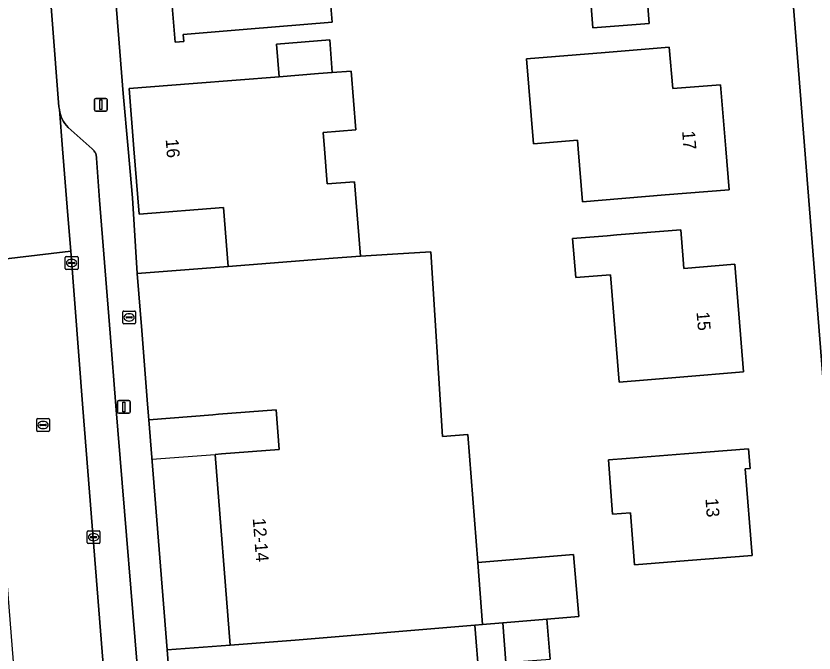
# Model space of a CAD drawing. Extents: x 157793 to 159380, y 380877 to 382313.
# Drawn here: x 158144.9 to 158207.1, y 381210.7 to 381260.3 of the extents above; entities that cross this region are included whole.
import ezdxf

# ---------------------------------------------------------------- set-up
doc = ezdxf.new("R2010")
doc.units = 0
for name, color, linetype in [('IMGEO_Brandkraan', 7, 'Continuous'), ('IMGEO_Erf', 7, 'Continuous'), ('IMGEO_Kolk', 7, 'Continuous'), ('IMGEO_Lichtmast', 7, 'Continuous'), ('IMGEO_Pand', 7, 'Continuous'), ('IMGEO_Pand_nummerreeks', 7, 'Continuous'), ('IMGEO_Pand_overbouw', 7, 'Continuous'), ('IMGEO_Parkeervlak_open', 7, 'Continuous'), ('IMGEO_Rijbaan_lokaal_gesloten', 7, 'Continuous'), ('IMGEO_Rioolput', 7, 'Continuous'), ('IMGEO_Voetpad_open', 7, 'Continuous')]:
    doc.layers.add(name, color=color, linetype=linetype)

msp = doc.modelspace()

# ---------------------------------------------------------------- linework, layer by layer
at = {"layer": 'IMGEO_Brandkraan'}
for p, q in [((158153.194, 381236.435), (158153.194, 381237.287)), ((158153.269, 381237.361), (158154.121, 381237.361)), ((158153.453, 381236.855), (158153.453, 381236.867)), ((158153.496, 381236.904), (158153.894, 381236.904)), ((158153.682, 381237.141), (158153.707, 381237.141)), ((158153.937, 381236.867), (158153.937, 381236.855)), ((158154.195, 381237.287), (158154.195, 381236.435)), ((158154.121, 381236.361), (158153.269, 381236.361)), ((158153.891, 381236.818), (158153.493, 381236.818)), ((158153.705, 381236.581), (158153.68, 381236.581))]:
    msp.add_line(p, q, dxfattribs=at)
for points in [[(158153.194, 381236.435), (158153.194, 381237.287)], [(158153.269, 381237.361), (158154.121, 381237.361)], [(158154.195, 381237.287), (158154.195, 381236.435)], [(158154.121, 381236.361), (158153.269, 381236.361)]]:
    msp.add_lwpolyline(points, dxfattribs=at)
for centre, radius, start, end in [((158153.271, 381237.285), 0.0765, 91.55205, 178.44795), ((158153.271, 381237.285), 0.0765, 91.55205, 178.44795), ((158153.493, 381236.864), 0.0403, 85.87752, 175.75265), ((158153.898, 381236.866), 0.0386, 1.73085, 96.63898), ((158154.119, 381237.285), 0.0765, 1.55205, 88.44795), ((158154.119, 381237.285), 0.0765, 1.55205, 88.44795), ((158153.271, 381236.437), 0.0765, 181.55205, 268.44795), ((158153.271, 381236.437), 0.0765, 181.55205, 268.44795), ((158153.49, 381236.854), 0.0366, 178.93798, 274.71019), ((158153.894, 381236.861), 0.043, 264.86636, 352.45326), ((158154.119, 381236.437), 0.0765, 271.55205, 358.44795), ((158154.119, 381236.437), 0.0765, 271.55205, 358.44795)]:
    msp.add_arc(centre, radius, start, end, dxfattribs=at)
for centre, major_axis, ratio, start_param, end_param in [((158153.681, 381236.861), (-0.387, 0.002), 0.722429, 4.712389, 7.853982), ((158153.706, 381236.861), (-0.39, 0.002), 0.717154, 1.570796, 4.712389)]:
    msp.add_ellipse(centre, major_axis=major_axis, ratio=ratio, start_param=start_param, end_param=end_param, dxfattribs=at)
at = {"layer": 'IMGEO_Erf'}
for points in [[(158217.503, 381108.594), (158207.836, 381230.9), (158200.897, 381318.677)], [(158168.188, 381275.758), (158169.503, 381259.859), (158162.895, 381259.313), (158157.911, 381258.901), (158157.957, 381258.343), (158157.27, 381258.287), (158156.726, 381264.864)], [(158151.631, 381274.599), (158153.242, 381254.297), (158153.62, 381250), (158153.955, 381246.186), (158154.327, 381240.281), (158161.404, 381240.838), (158161.045, 381245.426), (158154.465, 381244.912), (158154.068, 381250), (158153.701, 381254.693), (158158.686, 381255.083), (158165.381, 381255.607), (158165.183, 381258.147), (158169.325, 381258.471), (158169.524, 381255.932), (158170.991, 381256.047), (158171.349, 381251.472), (158168.814, 381251.273), (158168.914, 381250), (158169.128, 381247.273), (158171.257, 381247.409), (158171.71, 381241.622), (158174.222, 381241.782), (158177.203, 381241.972), (158178.12, 381227.586), (158180.078, 381227.739), (158180.857, 381217.78), (158188.317, 381218.406), (158188.723, 381213.573), (158186.249, 381213.365), (158186.492, 381210.258)], [(158183.047, 381209.988), (158182.805, 381213.077), (158181.235, 381212.945), (158180.637, 381212.898), (158180.967, 381208.681)]]:
    msp.add_lwpolyline(points, dxfattribs=at)
for points in [[(158182.446, 381266.828), (158181.783, 381275.315), (158186.626, 381275.693), (158191.61, 381276.082), (158191.916, 381272.173), (158198.287, 381272.671), (158198.947, 381264.211), (158193.902, 381263.817), (158194.219, 381259.76), (158189.827, 381259.417), (158189.51, 381263.474), (158189.207, 381267.356)], [(158189.027, 381245.874), (158188.689, 381250), (158188.635, 381250.662), (158185.197, 381250.38), (158184.655, 381256.988), (158190.795, 381257.491), (158195.778, 381257.9), (158196.042, 381254.682), (158199.768, 381254.987), (158200.177, 381250), (158200.439, 381246.81), (158195.456, 381246.401)], [(158188.486, 381239.97), (158188.241, 381243.01), (158190.944, 381243.228), (158191.694, 381243.288), (158196.677, 381243.69), (158196.852, 381241.365), (158196.904, 381240.676), (158200.884, 381241.003), (158201.571, 381232.617), (158196.588, 381232.208), (158191.875, 381231.822), (158191.192, 381240.189)], [(158160.403, 381226.199), (158160.902, 381226.238), (158165.388, 381226.589), (158165.147, 381229.669), (158160.662, 381229.318), (158160.215, 381229.283), (158155.23, 381228.893), (158155.463, 381225.953), (158156.652, 381210.965), (158161.565, 381211.348)], [(158191.03, 381225.77), (158192.426, 381225.879), (158196.971, 381226.235), (158201.955, 381226.625), (158202.075, 381225.095), (158201.701, 381225.066), (158202.229, 381218.318), (158197.245, 381217.928), (158193.074, 381217.602), (158192.757, 381221.652), (158191.361, 381221.543)]]:
    msp.add_lwpolyline(points, close=True, dxfattribs=at)
at = {"layer": 'IMGEO_Kolk'}
for p, q in [((158148.71, 381240.679), (158148.71, 381241.531)), ((158148.785, 381241.605), (158149.637, 381241.605)), ((158149.198, 381241.385), (158149.223, 381241.385)), ((158149.711, 381241.531), (158149.711, 381240.679)), ((158149.637, 381240.605), (158148.785, 381240.605)), ((158148.969, 381241.099), (158148.969, 381241.111)), ((158149.407, 381241.062), (158149.009, 381241.062)), ((158149.012, 381241.148), (158149.41, 381241.148)), ((158149.221, 381240.825), (158149.196, 381240.825)), ((158149.453, 381241.111), (158149.453, 381241.099)), ((158150.42, 381219.324), (158150.42, 381220.176)), ((158150.495, 381220.25), (158151.347, 381220.25)), ((158151.421, 381220.176), (158151.421, 381219.324)), ((158150.679, 381219.744), (158150.679, 381219.756)), ((158151.117, 381219.707), (158150.719, 381219.707)), ((158150.722, 381219.793), (158151.12, 381219.793)), ((158150.931, 381219.47), (158150.906, 381219.47)), ((158150.908, 381220.03), (158150.933, 381220.03)), ((158151.163, 381219.756), (158151.163, 381219.744)), ((158151.347, 381219.25), (158150.495, 381219.25))]:
    msp.add_line(p, q, dxfattribs=at)
for points in [[(158148.71, 381240.679), (158148.71, 381241.531)], [(158148.785, 381241.605), (158149.637, 381241.605)], [(158149.711, 381241.531), (158149.711, 381240.679)], [(158149.637, 381240.605), (158148.785, 381240.605)], [(158150.42, 381219.324), (158150.42, 381220.176)], [(158150.495, 381220.25), (158151.347, 381220.25)], [(158151.421, 381220.176), (158151.421, 381219.324)], [(158151.347, 381219.25), (158150.495, 381219.25)]]:
    msp.add_lwpolyline(points, dxfattribs=at)
for centre, radius, start, end in [((158148.787, 381241.529), 0.0765, 91.55205, 178.44795), ((158148.787, 381241.529), 0.0765, 91.55205, 178.44795), ((158149.635, 381241.529), 0.0765, 1.55205, 88.44795), ((158149.635, 381241.529), 0.0765, 1.55205, 88.44795), ((158148.787, 381240.681), 0.0765, 181.55205, 268.44795), ((158148.787, 381240.681), 0.0765, 181.55205, 268.44795), ((158149.009, 381241.108), 0.0403, 85.87752, 175.75265), ((158149.006, 381241.098), 0.0366, 178.93798, 274.71019), ((158149.41, 381241.105), 0.043, 264.86636, 352.45326), ((158149.414, 381241.11), 0.0386, 1.73085, 96.63898), ((158149.635, 381240.681), 0.0765, 271.55205, 358.44795), ((158149.635, 381240.681), 0.0765, 271.55205, 358.44795), ((158150.497, 381220.174), 0.0765, 91.55205, 178.44795), ((158150.497, 381220.174), 0.0765, 91.55205, 178.44795), ((158151.345, 381220.174), 0.0765, 1.55205, 88.44795), ((158151.345, 381220.174), 0.0765, 1.55205, 88.44795), ((158150.719, 381219.753), 0.0403, 85.87752, 175.75265), ((158150.716, 381219.743), 0.0366, 178.93798, 274.71019), ((158151.12, 381219.75), 0.043, 264.86636, 352.45326), ((158151.124, 381219.755), 0.0386, 1.73085, 96.63898), ((158150.497, 381219.326), 0.0765, 181.55205, 268.44795), ((158150.497, 381219.326), 0.0765, 181.55205, 268.44795), ((158151.345, 381219.326), 0.0765, 271.55205, 358.44795), ((158151.345, 381219.326), 0.0765, 271.55205, 358.44795)]:
    msp.add_arc(centre, radius, start, end, dxfattribs=at)
for centre, major_axis, ratio, start_param, end_param in [((158149.197, 381241.105), (-0.387, 0.002), 0.722429, 4.712389, 7.853982), ((158149.222, 381241.105), (-0.39, 0.002), 0.717154, 1.570796, 4.712389), ((158150.907, 381219.75), (-0.387, 0.002), 0.722429, 4.712389, 7.853982), ((158150.932, 381219.75), (-0.39, 0.002), 0.717154, 1.570796, 4.712389)]:
    msp.add_ellipse(centre, major_axis=major_axis, ratio=ratio, start_param=start_param, end_param=end_param, dxfattribs=at)
at = {"layer": 'IMGEO_Lichtmast'}
for p, q in [((158150.987, 381253.02), (158150.987, 381253.82)), ((158150.987, 381253.82), (158150.987, 381253.02)), ((158151.087, 381253.92), (158151.877, 381253.92)), ((158151.877, 381253.92), (158151.087, 381253.92)), ((158151.977, 381253.82), (158151.977, 381253.02)), ((158151.977, 381253.02), (158151.977, 381253.82)), ((158151.877, 381252.92), (158151.087, 381252.92)), ((158151.087, 381252.92), (158151.877, 381252.92)), ((158152.792, 381229.494), (158152.792, 381230.294)), ((158152.792, 381230.294), (158152.792, 381229.494)), ((158152.892, 381230.394), (158153.682, 381230.394)), ((158153.682, 381230.394), (158152.892, 381230.394)), ((158153.782, 381230.294), (158153.782, 381229.494)), ((158153.782, 381229.494), (158153.782, 381230.294)), ((158153.682, 381229.394), (158152.892, 381229.394)), ((158152.892, 381229.394), (158153.682, 381229.394))]:
    msp.add_line(p, q, dxfattribs=at)
for points in [[(158151.407, 381253.795), (158151.557, 381253.795), (158151.557, 381253.045), (158151.407, 381253.045), (158151.407, 381253.795)], [(158153.212, 381230.269), (158153.362, 381230.269), (158153.362, 381229.519), (158153.212, 381229.519), (158153.212, 381230.269)]]:
    msp.add_lwpolyline(points, dxfattribs=at)
for centre, start, end in [((158151.087, 381253.82), 90, 180), ((158151.087, 381253.82), 90, 180), ((158151.877, 381253.82), 0, 90), ((158151.877, 381253.82), 360, 90), ((158151.087, 381253.02), 180, 270), ((158151.087, 381253.02), 180, 270), ((158151.877, 381253.02), 270, 0), ((158151.877, 381253.02), 270, 0), ((158152.892, 381230.294), 90, 180), ((158152.892, 381230.294), 90, 180), ((158153.682, 381230.294), 0, 90), ((158153.682, 381230.294), 360, 90), ((158152.892, 381229.494), 180, 270), ((158152.892, 381229.494), 180, 270), ((158153.682, 381229.494), 270, 0), ((158153.682, 381229.494), 270, 0)]:
    msp.add_arc(centre, 0.1, start, end, dxfattribs=at)
at = {"layer": 'IMGEO_Pand'}
for points in [[(158193.902, 381263.817), (158198.947, 381264.211), (158198.287, 381272.671), (158191.916, 381272.173), (158191.61, 381276.082), (158186.626, 381275.693), (158181.783, 381275.315), (158182.446, 381266.828), (158189.207, 381267.356), (158189.51, 381263.474), (158189.827, 381259.417), (158194.219, 381259.76)], [(158163.343, 381275.531), (158156.582, 381274.995), (158156.623, 381274.491), (158156.705, 381273.503), (158157.03, 381269.555), (158156.433, 381269.506), (158156.548, 381268.101), (158157.147, 381268.15), (158157.414, 381264.921), (158156.726, 381264.864), (158157.27, 381258.287), (158157.957, 381258.343), (158157.911, 381258.901), (158162.895, 381259.313), (158169.503, 381259.859), (158168.188, 381275.758), (158163.357, 381275.358)], [(158165.381, 381255.607), (158168.456, 381255.848), (158169.524, 381255.932), (158169.325, 381258.471), (158165.183, 381258.147)], [(158195.456, 381246.401), (158200.439, 381246.81), (158200.177, 381250), (158199.768, 381254.987), (158196.042, 381254.682), (158195.778, 381257.9), (158190.795, 381257.491), (158184.655, 381256.988), (158185.197, 381250.38), (158188.635, 381250.662), (158188.689, 381250), (158189.027, 381245.874)], [(158168.914, 381250), (158168.814, 381251.273), (158171.349, 381251.472), (158170.991, 381256.047), (158169.524, 381255.932), (158168.456, 381255.848), (158165.381, 381255.607), (158158.686, 381255.083), (158153.701, 381254.693), (158154.068, 381250), (158154.465, 381244.912), (158161.045, 381245.426), (158161.404, 381240.838), (158169.581, 381241.486), (158171.71, 381241.622), (158171.257, 381247.409), (158169.128, 381247.273)], [(158196.588, 381232.208), (158201.571, 381232.617), (158200.884, 381241.003), (158196.904, 381240.676), (158196.852, 381241.365), (158196.677, 381243.69), (158191.694, 381243.288), (158190.944, 381243.228), (158188.241, 381243.01), (158188.486, 381239.97), (158191.192, 381240.189), (158191.875, 381231.822)], [(158180.078, 381227.739), (158178.12, 381227.586), (158177.203, 381241.972), (158174.222, 381241.782), (158171.71, 381241.622), (158169.581, 381241.486), (158161.404, 381240.838), (158154.327, 381240.281), (158154.678, 381235.849), (158155.133, 381230.111), (158155.23, 381228.893), (158160.215, 381229.283), (158160.662, 381229.318), (158165.147, 381229.669), (158165.388, 381226.589), (158160.902, 381226.238), (158160.403, 381226.199), (158161.565, 381211.348), (158166.64, 381211.724), (158180.637, 381212.898), (158181.235, 381212.945), (158180.857, 381217.78)], [(158192.426, 381225.879), (158191.03, 381225.77), (158191.361, 381221.543), (158192.757, 381221.652), (158193.074, 381217.602), (158197.245, 381217.928), (158202.229, 381218.318), (158201.701, 381225.066), (158202.075, 381225.095), (158201.955, 381226.625), (158196.971, 381226.235)], [(158180.857, 381217.78), (158181.235, 381212.945), (158182.805, 381213.077), (158186.249, 381213.365), (158188.723, 381213.573), (158188.317, 381218.406)], [(158186.249, 381213.365), (158182.805, 381213.077), (158183.047, 381209.988), (158186.492, 381210.258)], [(158168.208, 381191.894), (158167.121, 381205.79), (158167.059, 381206.571), (158180.048, 381207.604), (158180.967, 381208.681), (158180.637, 381212.898), (158166.64, 381211.724), (158161.565, 381211.348), (158156.652, 381210.965), (158157.055, 381205.871), (158157.839, 381195.954), (158158.231, 381190.999), (158168.216, 381191.793)]]:
    msp.add_lwpolyline(points, close=True, dxfattribs=at)
at = {"layer": 'IMGEO_Pand_overbouw'}
msp.add_lwpolyline([(158155.23, 381228.893), (158155.475, 381225.813), (158160.403, 381226.199), (158160.902, 381226.238), (158165.388, 381226.589), (158165.147, 381229.669), (158160.215, 381229.283)], close=True, dxfattribs=at)
at = {"layer": 'IMGEO_Parkeervlak_open'}
msp.add_lwpolyline([(158154.645, 381205.675), (158152.668, 381229.964), (158152.205, 381235.63), (158151.398, 381245.984), (158151.146, 381249.276), (158151.143, 381249.357), (158151.134, 381249.437), (158151.117, 381249.516), (158151.093, 381249.593), (158151.062, 381249.667), (158151.025, 381249.739), (158150.981, 381249.807), (158150.932, 381249.871), (158150.877, 381249.93), (158150.817, 381249.984), (158148.949, 381251.662), (158148.813, 381251.803), (158148.69, 381251.956), (158148.581, 381252.119), (158148.486, 381252.291), (158148.408, 381252.471), (158148.346, 381252.658), (158148.301, 381252.849), (158148.273, 381253.043), (158148.512, 381250), (158148.922, 381244.787), (158149.14, 381242.015), (158150.099, 381229.806), (158160.265, 381101.527)], dxfattribs=at)
at = {"layer": 'IMGEO_Rijbaan_lokaal_gesloten'}
msp.add_lwpolyline([(158138.872, 381280.436), (158142.335, 381241.215), (158149.14, 381242.015), (158148.922, 381244.787), (158148.512, 381250), (158148.273, 381253.043), (158148.225, 381253.262), (158146.678, 381273.28)], dxfattribs=at)
msp.add_lwpolyline([(158150.099, 381229.806), (158149.14, 381242.015), (158142.335, 381241.215), (158142.257, 381240.094), (158144.014, 381218.239), (158144.068, 381217.534), (158144.104, 381216.957), (158152.577, 381109.874), (158152.586, 381109.766), (158154.041, 381092.18), (158154.127, 381091.136), (158154.165, 381090.674), (158154.179, 381090.5), (158156.578, 381060.941), (158164.18, 381061.511), (158163.518, 381070.346), (158163.463, 381070.73), (158160.906, 381093.85), (158160.761, 381094.91), (158160.265, 381101.527)], close=True, dxfattribs=at)
at = {"layer": 'IMGEO_Rioolput'}
for p, q in [((158146.49, 381228.062), (158146.49, 381228.914)), ((158146.565, 381228.988), (158147.417, 381228.988)), ((158147.491, 381228.914), (158147.491, 381228.062)), ((158146.749, 381228.482), (158146.749, 381228.494)), ((158147.187, 381228.445), (158146.789, 381228.445)), ((158146.792, 381228.531), (158147.19, 381228.531)), ((158147.001, 381228.208), (158146.976, 381228.208)), ((158146.978, 381228.768), (158147.003, 381228.768)), ((158147.233, 381228.494), (158147.233, 381228.482)), ((158147.417, 381227.988), (158146.565, 381227.988))]:
    msp.add_line(p, q, dxfattribs=at)
for points in [[(158146.49, 381228.062), (158146.49, 381228.914)], [(158146.565, 381228.988), (158147.417, 381228.988)], [(158147.491, 381228.914), (158147.491, 381228.062)], [(158147.417, 381227.988), (158146.565, 381227.988)]]:
    msp.add_lwpolyline(points, dxfattribs=at)
for centre, radius, start, end in [((158146.567, 381228.912), 0.0765, 91.55205, 178.44795), ((158146.567, 381228.912), 0.0765, 91.55205, 178.44795), ((158147.415, 381228.912), 0.0765, 1.55205, 88.44795), ((158147.415, 381228.912), 0.0765, 1.55205, 88.44795), ((158146.789, 381228.491), 0.0403, 85.87752, 175.75265), ((158146.786, 381228.481), 0.0366, 178.93798, 274.71019), ((158147.19, 381228.488), 0.043, 264.86636, 352.45326), ((158147.194, 381228.493), 0.0386, 1.73085, 96.63898), ((158146.567, 381228.064), 0.0765, 181.55205, 268.44795), ((158146.567, 381228.064), 0.0765, 181.55205, 268.44795), ((158147.415, 381228.064), 0.0765, 271.55205, 358.44795), ((158147.415, 381228.064), 0.0765, 271.55205, 358.44795)]:
    msp.add_arc(centre, radius, start, end, dxfattribs=at)
for centre, major_axis, ratio, start_param, end_param in [((158146.977, 381228.488), (-0.387, 0.002), 0.722429, 4.712389, 7.853982), ((158147.002, 381228.488), (-0.39, 0.002), 0.717154, 1.570796, 4.712389)]:
    msp.add_ellipse(centre, major_axis=major_axis, ratio=ratio, start_param=start_param, end_param=end_param, dxfattribs=at)
at = {"layer": 'IMGEO_Voetpad_open'}
for points in [[(158205.551, 381319.116), (158200.897, 381318.677), (158207.836, 381230.9), (158217.503, 381108.594), (158220.532, 381108.688), (158219.558, 381120.837), (158219.539, 381121.075), (158231.062, 381121.965)], [(158157.055, 381205.871), (158156.652, 381210.965), (158155.463, 381225.953), (158155.23, 381228.893), (158155.133, 381230.111), (158154.678, 381235.849), (158154.327, 381240.281), (158153.955, 381246.186), (158153.62, 381250), (158153.242, 381254.297), (158151.631, 381274.599)], [(158146.678, 381273.28), (158148.225, 381253.262), (158148.273, 381253.043), (158148.301, 381252.849), (158148.346, 381252.658), (158148.408, 381252.471), (158148.486, 381252.291), (158148.581, 381252.119), (158148.69, 381251.956), (158148.813, 381251.803), (158148.949, 381251.662), (158150.817, 381249.984), (158150.877, 381249.93), (158150.932, 381249.871), (158150.981, 381249.807), (158151.025, 381249.739), (158151.062, 381249.667), (158151.093, 381249.593), (158151.117, 381249.516), (158151.134, 381249.437), (158151.143, 381249.357), (158151.146, 381249.276), (158151.398, 381245.984), (158152.205, 381235.63), (158152.668, 381229.964), (158154.645, 381205.675)]]:
    msp.add_lwpolyline(points, dxfattribs=at)

# ---------------------------------------------------------------- texts
at = {"layer": 'IMGEO_Pand_nummerreeks'}
for s, rotation, p in [('17', 274.69115, (158196.774, 381251.363)), ('16', 274.46886, (158156.539, 381250.733)), ('15', 274.68334, (158197.898, 381237.275)), ('13', 274.47402, (158198.591, 381222.751)), ('12-14', 274.47459, (158163.321, 381221.202))]:
    msp.add_text(s, height=1, rotation=rotation, dxfattribs=at).set_placement(p)

doc.saveas('drawing.dxf')
